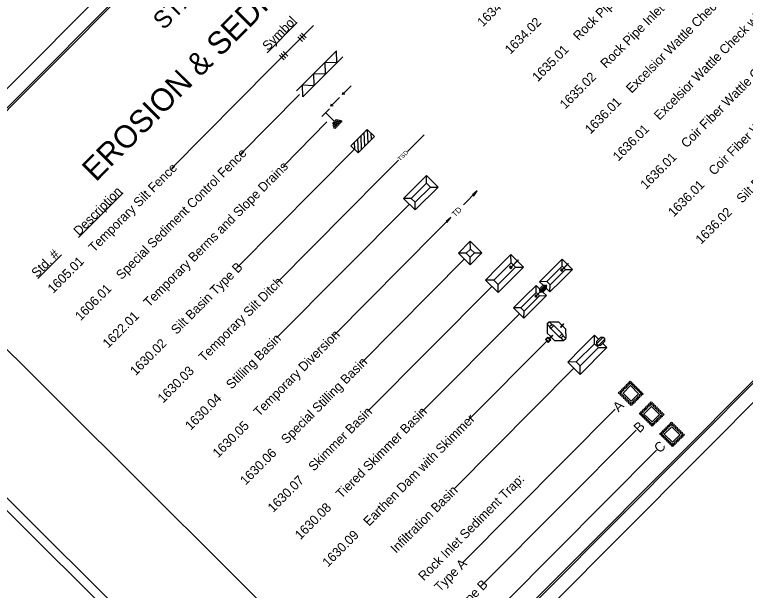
# Model space of a CAD drawing. Extents: x 1484932 to 1495672, y 495497 to 506262.
# Drawn here: x 1490730 to 1493934, y 501407 to 503930 of the extents above; entities that cross this region are included whole.
import ezdxf

# ---------------------------------------------------------------- set-up
doc = ezdxf.new("R2010")
doc.units = 0
for name, color, linetype in [('Scratch_Level_0', 7, 'Continuous'), ('Sheet Plot Border Inside CELL', 7, 'Continuous'), ('Sheet Plot Border Outside CELL', 7, 'Continuous')]:
    doc.layers.add(name, color=color, linetype=linetype)

msp = doc.modelspace()

# ---------------------------------------------------------------- linework, layer by layer
at = {"layer": 'Scratch_Level_0'}
for p, q in [((1491837.8, 503763.5), (1491969.7, 503896.1)), ((1491858.5, 503700.2), (1492040, 503882.4)), ((1491988.1, 503849.6), (1492008.7, 503829.2)), ((1491972.1, 503833.4), (1491992.5, 503813.1)), ((1491980.4, 503841.8), (1492000.8, 503821.5)), ((1491899.4, 503760.5), (1491919.8, 503740.1)), ((1491907.2, 503768.2), (1491927.6, 503747.9)), ((1491966.7, 503596.7), (1492141.7, 503772.2)), ((1492143.7, 503720.3), (1492141.7, 503772.2)), ((1491891.1, 503752.1), (1491911.5, 503731.7)), ((1491994.2, 503570.2), (1492168.6, 503745.4)), ((1492093.8, 503670.3), (1492091.8, 503722.2)), ((1492091.8, 503722.2), (1492143.7, 503720.3)), ((1491418.9, 503256.5), (1491858.5, 503700.2)), ((1492044, 503620.2), (1492042, 503672.1)), ((1492042, 503672.1), (1492093.8, 503670.3)), ((1491994.2, 503570.2), (1491992.2, 503622.1)), ((1491992.2, 503622.1), (1492044, 503620.2)), ((1491717.6, 503315.3), (1491979.1, 503580.1)), ((1492168.3, 503580.4), (1492170.2, 503590.7)), ((1492178.6, 503582.3), (1492168.3, 503580.4)), ((1492116.7, 503528.6), (1492119.2, 503539.4)), ((1492116.7, 503528.6), (1492119.2, 503539.4)), ((1492127.6, 503531), (1492116.7, 503528.6)), ((1492127.6, 503531), (1492116.7, 503528.6)), ((1492077.5, 503483.3), (1492111.4, 503517.2)), ((1492132, 503463.4), (1492095.3, 503499.9)), ((1491909.3, 503266.8), (1492099.6, 503460.1)), ((1492204.5, 503355.6), (1492276.1, 503427.5)), ((1492261.7, 503413), (1492264.7, 503353.4)), ((1492276.1, 503427.5), (1492279.2, 503367.9)), ((1492276.1, 503427.5), (1492307.4, 503396.4)), ((1492291.8, 503411.9), (1492293, 503381.9)), ((1492452.8, 503330.9), (1492525.2, 503403.6)), ((1492219.6, 503369.5), (1492220.2, 503340)), ((1492233.4, 503384.6), (1492235.8, 503324.5)), ((1492235.8, 503324.5), (1492307.4, 503396.4)), ((1492247.9, 503399), (1492250.2, 503339)), ((1491707.7, 502823.2), (1492220.2, 503340)), ((1492204.5, 503355.6), (1492235.8, 503324.5)), ((1492340.7, 503220), (1492413.1, 503292.7)), ((1491881.5, 502756.6), (1492340.7, 503220)), ((1492435.4, 503125.1), (1492535.5, 503225.6)), ((1492536.3, 503191.5), (1492535.5, 503225.6)), ((1492535.5, 503225.6), (1492586.6, 503174.7)), ((1491011.1, 502953.7), (1491206.4, 503149.8)), ((1492586.6, 503174.7), (1492486.5, 503074.2)), ((1492553.1, 503174.8), (1492586.6, 503174.7)), ((1492698.4, 503096.9), (1492758.8, 503157.6)), ((1492758.8, 503157.6), (1492738.2, 503140.6)), ((1492742.9, 503136.9), (1492758.8, 503157.6)), ((1492469.5, 503124.5), (1492435.4, 503125.1)), ((1492469.5, 503124.5), (1492435.4, 503125.1)), ((1492486.5, 503074.2), (1492435.4, 503125.1)), ((1492486.5, 503074.2), (1492435.4, 503125.1)), ((1492538.2, 503126.1), (1492486.5, 503074.2)), ((1492738.2, 503140.6), (1492742.9, 503136.9)), ((1491878.7, 502513.4), (1492461, 503099.7)), ((1492486.5, 503074.2), (1492486.3, 503107.7)), ((1492486.5, 503074.2), (1492486.3, 503107.7)), ((1492581.8, 502979.9), (1492642.3, 503040.7)), ((1492642.3, 503040.7), (1492621.7, 503023.5)), ((1492621.7, 503023.5), (1492625.8, 503019.3)), ((1492625.8, 503019.3), (1492642.3, 503040.7)), ((1492130.8, 502524.8), (1492581.8, 502979.9)), ((1492728.2, 502936.9), (1492676.5, 502885)), ((1492779.2, 502886), (1492728.2, 502936.9)), ((1492728.9, 502902.7), (1492728.2, 502936.9)), ((1490831.7, 502773.6), (1490935.6, 502878.1)), ((1492251.9, 502406.3), (1492702.1, 502859.6)), ((1492727.6, 502834.1), (1492676.5, 502885)), ((1492710.6, 502884.4), (1492676.5, 502885)), ((1492727.6, 502834.1), (1492727.4, 502867.6)), ((1492779.2, 502886), (1492727.6, 502834.1)), ((1492745.8, 502886.1), (1492779.2, 502886)), ((1492850.8, 502822.8), (1492906.5, 502878.6)), ((1492906.5, 502878.6), (1492961.4, 502823.9)), ((1492907.6, 502842.1), (1492906.5, 502878.6)), ((1493081.3, 502809.1), (1493130.7, 502858.6)), ((1493130.5, 502827.4), (1493130.7, 502858.6)), ((1493130.7, 502858.6), (1493175.8, 502813.7)), ((1492831.8, 502765.9), (1492907.7, 502841.9)), ((1492925.5, 502824.2), (1492849.7, 502748.2)), ((1492905.5, 502828.1), (1492900.2, 502822.8)), ((1492905.6, 502826.2), (1492902.1, 502822.7)), ((1492911.7, 502821.9), (1492905.5, 502828.1)), ((1492909.8, 502822), (1492905.6, 502826.2)), ((1492961.5, 502824), (1492905.8, 502768.1)), ((1492907.7, 502841.9), (1492925.5, 502824.2)), ((1492908.1, 502825.5), (1492937.6, 502855)), ((1492938.6, 502854), (1492909.1, 502824.5)), ((1492925.5, 502824.2), (1492961.4, 502823.9)), ((1492937.6, 502855), (1492938.6, 502854)), ((1493063.3, 502760), (1493130.6, 502827.3)), ((1493130.4, 502813.3), (1493156.5, 502839.4)), ((1493130.6, 502827.3), (1493145.2, 502812.8)), ((1493157.3, 502838.6), (1493131.2, 502812.5)), ((1493156.5, 502839.4), (1493157.3, 502838.6)), ((1492795.1, 502766.9), (1492850.8, 502822.8)), ((1492900.2, 502822.8), (1492906.4, 502816.6)), ((1492902.1, 502822.7), (1492906.3, 502818.5)), ((1492906.3, 502818.5), (1492909.8, 502822)), ((1492906.4, 502816.6), (1492911.7, 502821.9)), ((1493032.1, 502759.7), (1493081.3, 502809.1)), ((1493145.2, 502812.8), (1493078, 502745.4)), ((1493128.2, 502815.5), (1493123.5, 502810.7)), ((1493123.5, 502810.7), (1493128.6, 502805.6)), ((1493128.2, 502813.8), (1493125.2, 502810.7)), ((1493125.2, 502810.7), (1493128.6, 502807.3)), ((1493175.9, 502813.7), (1493126.6, 502764.2)), ((1493133.3, 502810.4), (1493128.2, 502815.5)), ((1493131.7, 502810.4), (1493128.2, 502813.8)), ((1493128.6, 502805.6), (1493133.3, 502810.4)), ((1493128.6, 502807.3), (1493131.7, 502810.4)), ((1493145.2, 502812.8), (1493175.8, 502813.7)), ((1492831.8, 502765.9), (1492795.1, 502766.9)), ((1492850.1, 502712.1), (1492795.1, 502766.9)), ((1492849.7, 502748.2), (1492831.8, 502765.9)), ((1492905.8, 502768.1), (1492850.1, 502712.1)), ((1493063.3, 502760), (1493032.1, 502759.7)), ((1493047.6, 502744.1), (1493032.1, 502759.7)), ((1493078, 502745.4), (1493063.3, 502760)), ((1493126.6, 502764.2), (1493077.2, 502714.7)), ((1492277.2, 502190.4), (1492822.6, 502739.5)), ((1492850.1, 502712.1), (1492849.8, 502748.2)), ((1492967, 502694.3), (1493016.3, 502743.8)), ((1493016.1, 502712.6), (1493016.3, 502743.8)), ((1493031.9, 502728.3), (1493016.3, 502743.8)), ((1493017.6, 502699.8), (1493062.4, 502744.7)), ((1493063.3, 502743.9), (1493018.4, 502698.9)), ((1493031.9, 502720.2), (1493055.6, 502744.2)), ((1493031.9, 502728.3), (1493047.6, 502744.1)), ((1493031.9, 502728.3), (1493031.9, 502720.2)), ((1493062.2, 502737.6), (1493038.5, 502713.7)), ((1493046.5, 502713.7), (1493062.2, 502729.6)), ((1493047.6, 502744.1), (1493055.6, 502744.2)), ((1493055.6, 502744.2), (1493062.2, 502737.6)), ((1493062.2, 502729.6), (1493062.2, 502737.6)), ((1493077.2, 502714.7), (1493062.2, 502729.6)), ((1493062.4, 502744.7), (1493063.3, 502743.9)), ((1493077.2, 502714.7), (1493078.1, 502745.4)), ((1492949, 502645.2), (1493016.2, 502712.4)), ((1493030.8, 502697.9), (1492963.6, 502630.6)), ((1493015.5, 502701.9), (1493010.7, 502697.1)), ((1493010.7, 502697.1), (1493015.8, 502692.1)), ((1493061.5, 502698.9), (1493012.2, 502649.4)), ((1493015.5, 502700.2), (1493012.4, 502697.1)), ((1493012.4, 502697.1), (1493015.8, 502693.7)), ((1493020.6, 502696.8), (1493015.5, 502701.9)), ((1493018.9, 502696.8), (1493015.5, 502700.2)), ((1493015.8, 502692.1), (1493020.6, 502696.8)), ((1493015.8, 502693.7), (1493018.9, 502696.8)), ((1493016.2, 502712.4), (1493030.8, 502697.9)), ((1493030.8, 502697.9), (1493061.5, 502698.8)), ((1493031.9, 502720.2), (1493038.5, 502713.7)), ((1493046.5, 502713.7), (1493038.5, 502713.7)), ((1493046.5, 502713.7), (1493061.5, 502698.8)), ((1492917.7, 502644.8), (1492967, 502694.3)), ((1492949, 502645.2), (1492917.7, 502644.8)), ((1492962.8, 502599.8), (1492917.7, 502644.8)), ((1492963.6, 502630.6), (1492949, 502645.2)), ((1493012.2, 502649.4), (1492962.8, 502599.8)), ((1492514, 502187.4), (1492943.2, 502619.5)), ((1492962.8, 502599.8), (1492963.7, 502630.6)), ((1493065.3, 502574.2), (1493074.4, 502583.4)), ((1493076, 502563.5), (1493065.3, 502574.2)), ((1493065.3, 502574.2), (1493065.7, 502533.9)), ((1493074.4, 502583.4), (1493115.1, 502583.5)), ((1493085.1, 502572.7), (1493074.4, 502583.4)), ((1493076, 502563.5), (1493085.1, 502572.7)), ((1493081, 502554.3), (1493094.8, 502568.1)), ((1493094.8, 502568.1), (1493085.1, 502572.7)), ((1493094.8, 502568.1), (1493131.1, 502532)), ((1493115.1, 502583.5), (1493130.2, 502568.5)), ((1493136.8, 502575.1), (1493123.1, 502561.3)), ((1493138.7, 502573.1), (1493125, 502559.4)), ((1493136.8, 502575.1), (1493138.7, 502573.1)), ((1493081, 502554.3), (1493076, 502563.5)), ((1493081, 502554.3), (1493117.3, 502518.2)), ((1493123, 502561.3), (1493125, 502559.4)), ((1493132.1, 502566.5), (1493146, 502552.7)), ((1493146, 502552.7), (1493146.4, 502511.5)), ((1493068.7, 502517.2), (1493057.3, 502505.8)), ((1493057.3, 502505.8), (1493069.6, 502493.5)), ((1493068.7, 502513.2), (1493061.3, 502505.8)), ((1493061.3, 502505.8), (1493069.6, 502497.6)), ((1493065.7, 502533.9), (1493080.7, 502519)), ((1493081, 502505), (1493068.7, 502517.2)), ((1493077, 502505), (1493068.7, 502513.2)), ((1493069.6, 502493.5), (1493081, 502505)), ((1493069.6, 502497.6), (1493077, 502505)), ((1493073.8, 502512.1), (1493087.8, 502526.1)), ((1493075.8, 502510.1), (1493089.8, 502524.1)), ((1493082.7, 502517), (1493097.5, 502502.3)), ((1493087.8, 502526.1), (1493089.8, 502524.1)), ((1493131.1, 502532), (1493117.3, 502518.1)), ((1493117.3, 502518.2), (1493126.6, 502513.1)), ((1493135.7, 502522.2), (1493126.6, 502513.1)), ((1493137.3, 502502.4), (1493126.6, 502513.1)), ((1493131.1, 502532), (1493135.7, 502522.2)), ((1493146.4, 502511.5), (1493135.7, 502522.2)), ((1493137.3, 502502.4), (1493146.4, 502511.5)), ((1493214, 502466.4), (1493272.7, 502525.4)), ((1493272.5, 502488.2), (1493272.7, 502525.4)), ((1493272.7, 502525.4), (1493291.3, 502506.8)), ((1493282, 502497.4), (1493300.7, 502516.3)), ((1493282, 502487.8), (1493310.2, 502516.3)), ((1493318.1, 502508.5), (1493289.8, 502480)), ((1493300.7, 502516.3), (1493310.2, 502516.3)), ((1493310.2, 502516.3), (1493318.1, 502508.5)), ((1493318.1, 502498.9), (1493318.1, 502508.5)), ((1492722.3, 502156.2), (1493063.4, 502499.7)), ((1493097.5, 502502.3), (1493137.3, 502502.4)), ((1493192.5, 502407.9), (1493272.6, 502488)), ((1493209, 502353.8), (1493326.5, 502471.8)), ((1493272.6, 502488), (1493290, 502470.7)), ((1493282, 502497.4), (1493282, 502487.8)), ((1493282, 502487.8), (1493289.8, 502480)), ((1493299.4, 502480.1), (1493289.8, 502480)), ((1493290, 502470.7), (1493326.5, 502471.8)), ((1493299.4, 502480.1), (1493318.1, 502498.9)), ((1493326.5, 502471.8), (1493308.7, 502489.6)), ((1493155.2, 502407.5), (1493214, 502466.4)), ((1493290, 502470.7), (1493210, 502390.5)), ((1493192.5, 502407.9), (1493155.2, 502407.5)), ((1493209, 502353.8), (1493155.2, 502407.5)), ((1493210, 502390.5), (1493192.5, 502407.9)), ((1492658.6, 501853.6), (1493182.1, 502380.6)), ((1493209, 502353.8), (1493210.1, 502390.5)), ((1492695, 501528.4), (1493363.2, 502201.1)), ((1492786.5, 501436.8), (1493454.9, 502109.8)), ((1492880.1, 501352.6), (1493544.1, 502021))]:
    msp.add_line(p, q, dxfattribs=at)
for points in [[(1493352.5, 506178.3), (1490172.1, 502984.8), (1492407.6, 500758.5), (1495587.9, 503952.1)], [(1492486.3, 503107.7), (1492469.5, 503124.5), (1492536.3, 503191.5), (1492553.1, 503174.8)], [(1492727.4, 502867.6), (1492710.6, 502884.4), (1492728.9, 502902.7), (1492745.8, 502886.1)], [(1493397.6, 502271.2), (1493430.4, 502304.2), (1493465.7, 502268.9), (1493433.6, 502236.5)], [(1493489.3, 502179.9), (1493522, 502212.9), (1493557, 502178.2), (1493525.3, 502145.2)], [(1493578.3, 502091.2), (1493611.1, 502124), (1493646.6, 502088.8), (1493614.4, 502056.4)]]:
    msp.add_lwpolyline(points, close=True, dxfattribs=at)
for points in [[(1492168.3, 503580.4), (1492206, 503618.3)], [(1492116.7, 503528.6), (1492154.4, 503566.5)], [(1492116.7, 503528.6), (1492154.4, 503566.5)]]:
    msp.add_lwpolyline(points, dxfattribs=at)
for centre, major_axis in [((1492135.2, 503460.4), (-3.12, 3.11)), ((1492141.6, 503466.7), (-3.12, 3.11)), ((1492150.8, 503465.1), (-3.12, 3.11)), ((1492159.9, 503462.6), (-3.12, 3.11)), ((1492129.4, 503454), (-3.12, 3.11)), ((1492131.7, 503444.7), (-3.12, 3.11)), ((1492133.9, 503435.4), (-3.12, 3.11)), ((1492138.2, 503451.3), (-3.12, 3.11)), ((1492140.4, 503442), (-3.12, 3.11)), ((1492144.3, 503457.4), (-3.12, 3.11)), ((1492146.8, 503448.4), (-3.12, 3.11)), ((1492153.5, 503456.3), (-3.12, 3.11)), ((1493416.2, 502306.2), (3.01, -3)), ((1493423, 502313), (3.01, -3)), ((1493429.7, 502319.7), (3.01, -3)), ((1493437, 502312.5), (3.01, -3)), ((1493389.2, 502279.1), (3.01, -3)), ((1493396, 502285.9), (3.01, -3)), ((1493402.7, 502292.7), (3.01, -3)), ((1493409.5, 502299.4), (3.01, -3)), ((1493444.3, 502305.2), (3.01, -3)), ((1493451.6, 502297.9), (3.01, -3)), ((1493458.9, 502290.7), (3.01, -3)), ((1493466.2, 502283.4), (3.01, -3)), ((1493473.5, 502276.1), (3.01, -3)), ((1493382.5, 502272.3), (3.01, -3)), ((1493389.8, 502265.1), (3.01, -3)), ((1493397.1, 502257.8), (3.01, -3)), ((1493404.4, 502250.5), (3.01, -3)), ((1493411.7, 502243.3), (3.01, -3)), ((1493460.6, 502248.5), (3.01, -3)), ((1493467.3, 502255.3), (3.01, -3)), ((1493474.1, 502262.1), (3.01, -3)), ((1493480.8, 502268.8), (3.01, -3)), ((1493419, 502236), (3.01, -3)), ((1493426.3, 502228.7), (3.01, -3)), ((1493433.6, 502221.5), (3.01, -3)), ((1493440.3, 502228.2), (3.01, -3)), ((1493447.1, 502235), (3.01, -3)), ((1493453.8, 502241.8), (3.01, -3)), ((1493507.6, 502215.2), (3.01, -3)), ((1493514.4, 502222), (3.01, -3)), ((1493521.1, 502228.8), (3.01, -3)), ((1493528.4, 502221.5), (3.01, -3)), ((1493535.7, 502214.2), (3.01, -3)), ((1493473.9, 502181.4), (3.01, -3)), ((1493480.7, 502188.1), (3.01, -3)), ((1493487.4, 502194.9), (3.01, -3)), ((1493494.2, 502201.7), (3.01, -3)), ((1493500.9, 502208.4), (3.01, -3)), ((1493543, 502206.9), (3.01, -3)), ((1493550.3, 502199.7), (3.01, -3)), ((1493557.6, 502192.4), (3.01, -3)), ((1493564.9, 502185.1), (3.01, -3)), ((1493481.2, 502174.1), (3.01, -3)), ((1493488.5, 502166.8), (3.01, -3)), ((1493495.8, 502159.6), (3.01, -3)), ((1493503.1, 502152.3), (3.01, -3)), ((1493545.3, 502150.8), (3.01, -3)), ((1493552, 502157.6), (3.01, -3)), ((1493558.7, 502164.3), (3.01, -3)), ((1493565.5, 502171.1), (3.01, -3)), ((1493572.2, 502177.9), (3.01, -3)), ((1493510.4, 502145), (3.01, -3)), ((1493517.7, 502137.8), (3.01, -3)), ((1493525, 502130.5), (3.01, -3)), ((1493531.8, 502137.3), (3.01, -3)), ((1493538.5, 502144), (3.01, -3)), ((1493590.3, 502119.4), (3.01, -3)), ((1493597, 502126.1), (3.01, -3)), ((1493603.8, 502132.9), (3.01, -3)), ((1493610.5, 502139.7), (3.01, -3)), ((1493617.8, 502132.4), (3.01, -3)), ((1493625.1, 502125.1), (3.01, -3)), ((1493632.4, 502117.9), (3.01, -3)), ((1493563.3, 502092.3), (3.01, -3)), ((1493570.1, 502099.1), (3.01, -3)), ((1493570.6, 502085), (3.01, -3)), ((1493576.8, 502105.8), (3.01, -3)), ((1493583.5, 502112.6), (3.01, -3)), ((1493639.7, 502110.6), (3.01, -3)), ((1493647, 502103.3), (3.01, -3)), ((1493654.3, 502096.1), (3.01, -3)), ((1493654.9, 502082), (3.01, -3)), ((1493661.6, 502088.8), (3.01, -3)), ((1493577.9, 502077.8), (3.01, -3)), ((1493585.2, 502070.5), (3.01, -3)), ((1493592.5, 502063.2), (3.01, -3)), ((1493599.8, 502055.9), (3.01, -3)), ((1493627.9, 502054.9), (3.01, -3)), ((1493634.6, 502061.7), (3.01, -3)), ((1493641.4, 502068.5), (3.01, -3)), ((1493648.1, 502075.3), (3.01, -3)), ((1493607.1, 502048.7), (3.01, -3)), ((1493614.4, 502041.4), (3.01, -3)), ((1493621.1, 502048.2), (3.01, -3))]:
    msp.add_ellipse(centre, major_axis=major_axis, ratio=0.927398, dxfattribs=at)
at = {"layer": 'Sheet Plot Border Inside CELL'}
msp.add_lwpolyline([(1492087.5, 500426.4), (1495619.8, 503973.4), (1493373.6, 506210.2), (1489841.3, 502663.3)], close=True, dxfattribs=at)
at = {"layer": 'Sheet Plot Border Outside CELL'}
msp.add_lwpolyline([(1492102.5, 500356.3), (1495671.9, 503940.6), (1493340.6, 506262.2), (1489771.2, 502678)], close=True, dxfattribs=at)

# ---------------------------------------------------------------- texts
at = {"layer": 'Scratch_Level_0'}
for s, height, p in [('EROSION & SEDIMENT CONTROL LEGEND', 99.051, (1491086.8, 503194.8)), ('STATE OF NORTH CAROLINA', 77.039, (1491383.9, 503859.9)), ('Rock Pipe Inlet Sediment Trap Type A', 40.704, (1493203.4, 503814.1)), ('Rock Pipe Inlet Sediment Trap Type B', 40.704, (1493322.9, 503693)), ('Excelsior Wattle Check with Flocculant', 40.761, (1493557.3, 503464.8)), ('1634.01', 40.71, (1492782.9, 503874.1)), ('Excelsior Wattle Check', 40.761, (1493435.1, 503583.3)), ('Symbol', 40.76, (1491840.9, 503770.3)), ('1634.02', 40.71, (1492903.5, 503754)), ('Coir Fiber Wattle Check with Flocculant', 40.761, (1493796.8, 503223.2)), ('1635.01', 40.71, (1493024, 503634)), ('Coir Fiber Wattle Check', 40.761, (1493676.2, 503343.2)), ('Silt Fence Excelsior Wattle Break', 40.777, (1493919.3, 503101.2)), ('1635.02', 40.71, (1493144.6, 503513.9)), ('1636.01', 40.71, (1493254.6, 503404.4)), ('1636.01', 40.71, (1493377.1, 503285.6)), ('Special Sediment Control Fence', 40.761, (1491199.4, 502766.1)), ('TSD', 19.05, (1492420.7, 503287.2)), ('1636.01', 40.71, (1493497.8, 503162.2)), ('Temporary Silt Fence', 40.761, (1491078.9, 502886.2)), ('Temporary Berms and Slope Drains ', 40.704, (1491320, 502646.1)), ('1636.01', 40.71, (1493619.3, 503041.2)), ('Description', 40.761, (1491012.6, 502958.9)), ('TD', 24.72, (1492661.8, 503041.7)), ('1636.02', 40.71, (1493739.8, 502921.1)), ('Std. #', 40.76, (1490828.7, 502775.6)), ('1605.01', 40.71, (1490899.5, 502706.1)), ('Silt Basin Type B', 40.761, (1491440.5, 502526)), ('Temporary Silt Ditch', 40.761, (1491561.1, 502406)), ('1606.01', 40.71, (1491020, 502586.1)), ('1622.01', 40.71, (1491140.6, 502466)), ('Temporary Diversion', 40.777, (1491802.2, 502165.9)), ('1630.02', 40.71, (1491261.1, 502346)), ('Stilling Basin', 40.761, (1491681.6, 502285.9)), ('Special Stilling Basin', 40.761, (1491922.7, 502045.8)), ('1630.03', 40.71, (1491381.7, 502225.9)), ('1630.04', 40.71, (1491502.2, 502105.9)), ('A', 42.9, (1493378.4, 502186)), ('Skimmer Basin', 40.761, (1492042.3, 501926.8)), ('Tiered Skimmer Basin', 40.761, (1492162.8, 501806.7)), ('1630.05', 40.71, (1491622.8, 501985.8)), ('Earthen Dam with Skimmer', 40.761, (1492284, 501685.7)), ('B', 42.9, (1493470.1, 502094.6)), ('C', 42.9, (1493559.3, 502005.9)), ('1630.06', 40.71, (1491743.3, 501865.8)), ('1630.07', 40.71, (1491863.9, 501745.7)), ('Rock Inlet Sediment Trap:', 40.704, (1492524.7, 501446.3)), ('Infiltration Basin', 40.761, (1492402.8, 501566.9)), ('1630.08', 40.71, (1491983.4, 501626.6)), ('1630.09', 40.71, (1492104, 501506.6)), (' Type A', 40.76, (1492583.9, 501387.4)), (' Type B', 40.76, (1492675.6, 501296.1))]:
    msp.add_text(s, height=height, rotation=45.1186, dxfattribs=at).set_placement(p)

doc.saveas('drawing.dxf')
